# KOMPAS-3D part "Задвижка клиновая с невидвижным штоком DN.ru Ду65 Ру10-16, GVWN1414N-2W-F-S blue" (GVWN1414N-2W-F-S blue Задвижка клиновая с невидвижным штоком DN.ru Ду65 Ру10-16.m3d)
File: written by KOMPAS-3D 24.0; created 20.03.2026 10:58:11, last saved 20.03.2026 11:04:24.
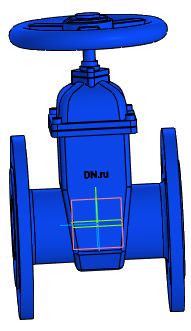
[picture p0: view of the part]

Document properties: Автор: R2D2; Полное имя файла: GVWN1414N-2W-F-S blue Задвижка клиновая с невидвижным штоком DN.ru Ду65 Ру10-16.cdw

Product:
- Part/product: Задвижка клиновая с невидвижным штоком DN.ru Ду65 Ру10-16  | designation GVWN1414N-2W-F-S blue
    Масса: 9
    Раздел спецификации: Прочие изделия
    Форматы листов документа: A3
    Примечание: D040-10580

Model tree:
1. Операция без истории:1

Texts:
  GVWN1414N-2W-F-S blue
